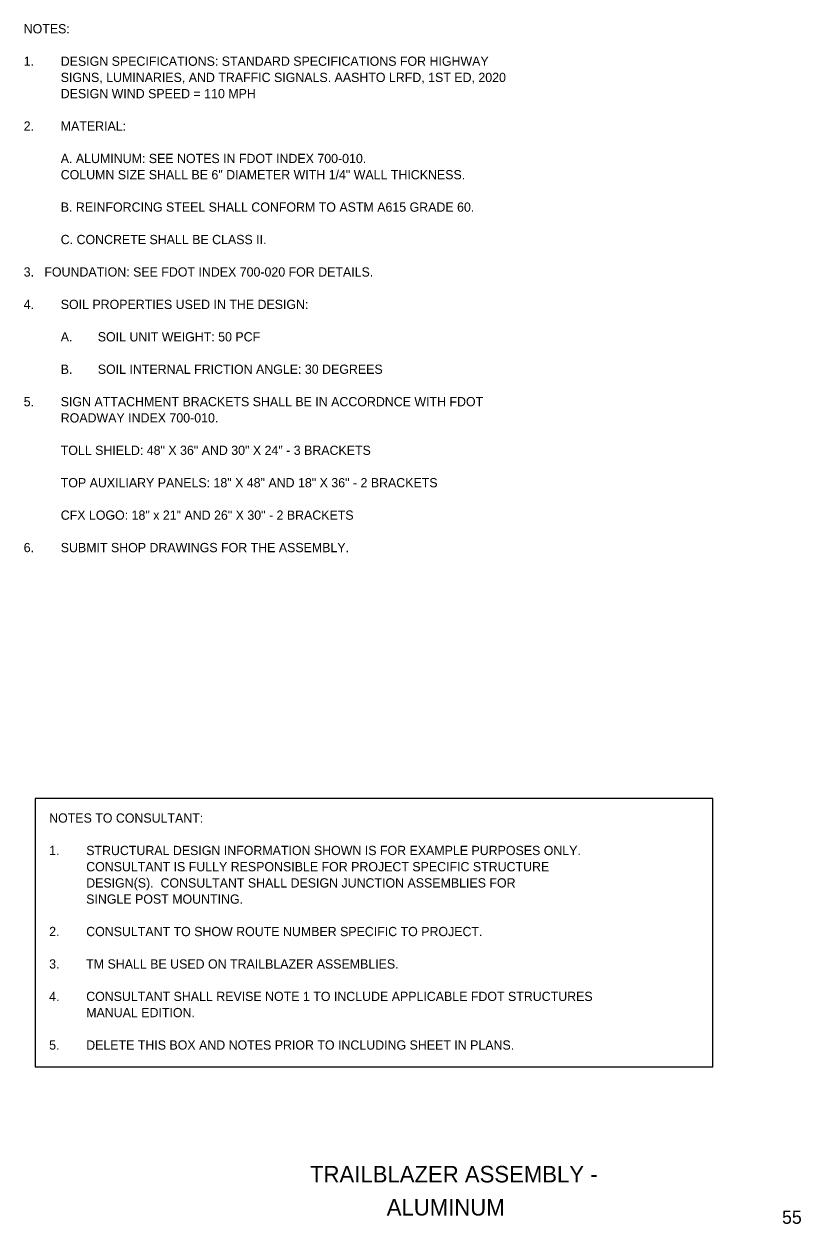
# Model space of a CAD drawing. Extents: x 52649 to 53276, y 9410 to 9783.
# Drawn here: x 53041.3 to 53276.3, y 9420.2 to 9782.8 of the extents above; entities that cross this region are included whole.
import ezdxf

# ---------------------------------------------------------------- set-up
doc = ezdxf.new("R2010")
doc.units = 0
for name, color, linetype in [('TextAlert', 7, 'Continuous'), ('TextMisc', 7, 'Continuous'), ('TextNotes', 7, 'Continuous'), ('TextShtNo', 7, 'Continuous')]:
    doc.layers.add(name, color=color, linetype=linetype)

msp = doc.modelspace()

# ---------------------------------------------------------------- linework, layer by layer
at = {"layer": 'TextAlert'}
msp.add_lwpolyline([(53044.7, 9467.65), (53249.61, 9467.65), (53249.61, 9548.74), (53044.7, 9548.74)], close=True, dxfattribs=at)

# ---------------------------------------------------------------- texts
for s, p in [('NOTES TO CONSULTANT:', (53048.93, 9541.45)), ('1.', (53048.93, 9531.65)), ('STRUCTURAL DESIGN INFORMATION SHOWN IS FOR EXAMPLE PURPOSES ONLY.', (53060.13, 9531.65)), ('CONSULTANT IS FULLY RESPONSIBLE FOR PROJECT SPECIFIC STRUCTURE', (53060.13, 9526.75)), ('DESIGN(S).  CONSULTANT SHALL DESIGN JUNCTION ASSEMBLIES FOR', (53060.13, 9521.85)), ('SINGLE POST MOUNTING.', (53060.13, 9516.95)), ('2.', (53048.93, 9507.15)), ('CONSULTANT TO SHOW ROUTE NUMBER SPECIFIC TO PROJECT.', (53060.13, 9507.15)), ('3.', (53048.93, 9497.35)), ('TM SHALL BE USED ON TRAILBLAZER ASSEMBLIES.', (53060.13, 9497.35)), ('4.', (53048.93, 9487.55)), ('CONSULTANT SHALL REVISE NOTE 1 TO INCLUDE APPLICABLE FDOT STRUCTURES', (53060.13, 9487.55)), ('MANUAL EDITION.', (53060.13, 9482.65)), ('5.', (53048.93, 9472.85)), ('DELETE THIS BOX AND NOTES PRIOR TO INCLUDING SHEET IN PLANS.', (53060.13, 9472.85))]:
    msp.add_text(s, height=2.8, dxfattribs=at).set_placement(p)
at = {"layer": 'TextMisc'}
for s, p in [(' TRAILBLAZER ASSEMBLY - ', (53125.95, 9432.71)), ('        ALUMINUM        ', (53136.14, 9422.71))]:
    msp.add_text(s, height=5, rotation=360, dxfattribs=at).set_placement(p)
at = {"layer": 'TextNotes'}
for s, p in [('NOTES:', (53041.23, 9780)), ('1.', (53041.23, 9770.2)), ('DESIGN SPECIFICATIONS: STANDARD SPECIFICATIONS FOR HIGHWAY', (53052.43, 9770.2)), ('SIGNS, LUMINARIES, AND TRAFFIC SIGNALS. AASHTO LRFD, 1ST ED, 2020', (53052.43, 9765.3)), ('DESIGN WIND SPEED = 110 MPH', (53052.43, 9760.4)), ('2.', (53041.23, 9750.6)), ('MATERIAL:', (53052.43, 9750.6)), ('A. ALUMINUM: SEE NOTES IN FDOT INDEX 700-010. ', (53052.43, 9740.8)), ('COLUMN SIZE SHALL BE 6" DIAMETER WITH 1/4" WALL THICKNESS.', (53052.43, 9735.9)), ('B. REINFORCING STEEL SHALL CONFORM TO ASTM A615 GRADE 60.', (53052.43, 9726.1)), ('C. CONCRETE SHALL BE CLASS II.', (53052.43, 9716.3)), ('3.   FOUNDATION: SEE FDOT INDEX 700-020 FOR DETAILS.', (53041.23, 9706.5)), ('4.', (53041.23, 9696.7)), ('SOIL PROPERTIES USED IN THE DESIGN:  ', (53052.43, 9696.7)), ('A.', (53052.43, 9686.9)), ('SOIL UNIT WEIGHT: 50 PCF', (53063.63, 9686.9)), ('B.', (53052.43, 9677.1)), ('SOIL INTERNAL FRICTION ANGLE: 30 DEGREES', (53063.63, 9677.1)), ('5. ', (53041.23, 9667.3)), ('SIGN ATTACHMENT BRACKETS SHALL BE IN ACCORDNCE WITH FDOT', (53052.43, 9667.3)), ('ROADWAY INDEX 700-010.', (53052.43, 9662.4)), ('TOLL SHIELD: 48" X 36" AND 30" X 24" - 3 BRACKETS', (53052.43, 9652.6)), ('TOP AUXILIARY PANELS: 18" X 48" AND 18" X 36" - 2 BRACKETS', (53052.43, 9642.8)), ('CFX LOGO: 18" x 21" AND 26" X 30" - 2 BRACKETS ', (53052.43, 9633)), ('6.', (53041.23, 9623.2)), ('SUBMIT SHOP DRAWINGS FOR THE ASSEMBLY.', (53052.43, 9623.2))]:
    msp.add_text(s, height=2.8, dxfattribs=at).set_placement(p)
at = {"layer": 'TextShtNo'}
msp.add_text('55', height=4, rotation=360, dxfattribs=at).set_placement((53270.54, 9420.21))

doc.saveas('drawing.dxf')
